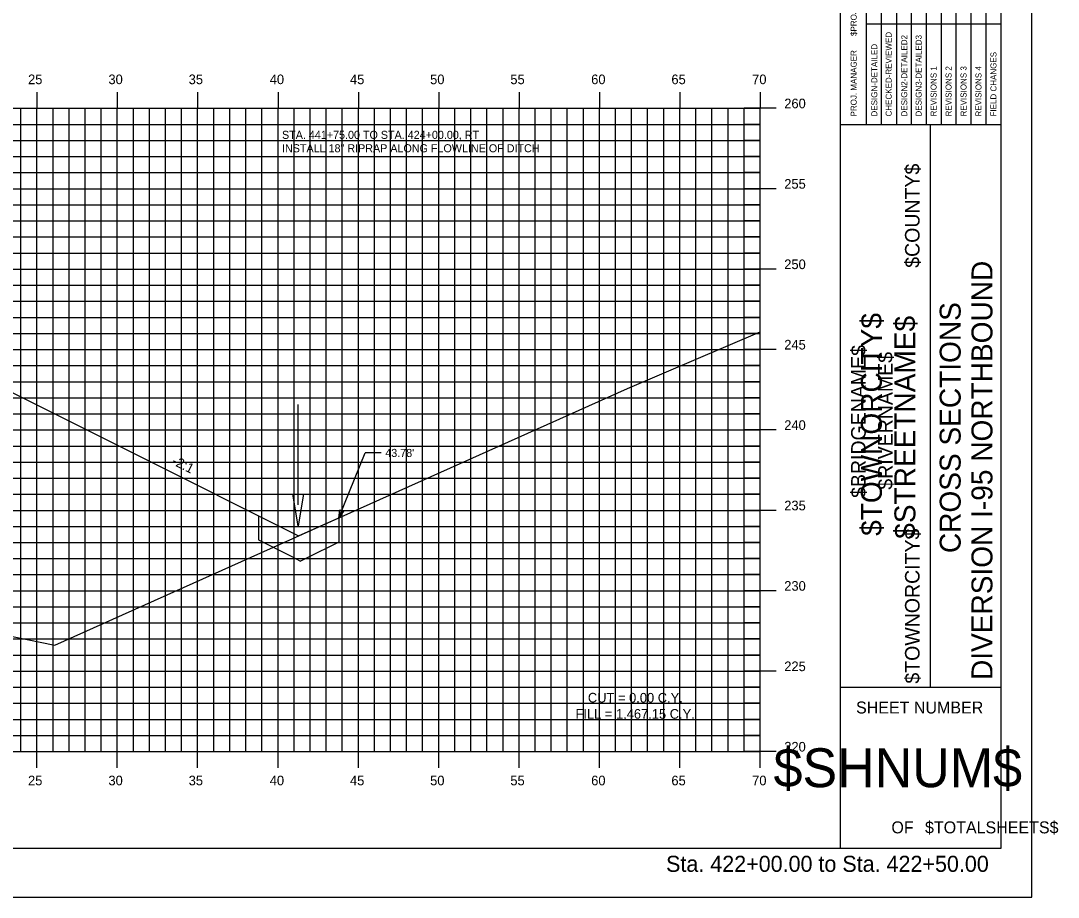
# Model space of a CAD drawing. Extents: x 1160718 to 1173142, y 616002 to 617630.
# Drawn here: x 1169986.4 to 1170050.9, y 616613.9 to 616668.4 of the extents above; entities that cross this region are included whole.
import ezdxf

# ---------------------------------------------------------------- set-up
doc = ezdxf.new("R2010")
doc.units = 0
for name, color, linetype in [('ANNOTATION', 7, 'Continuous'), ('BORDER', 7, 'Continuous'), ('BRIDGE_TITLE', 7, 'Continuous'), ('D_Drainage_Ditch_Line', 7, 'Continuous'), ('D_Roadway_Centerline', 7, 'Continuous'), ('H_V ANNOTATION', 7, 'Continuous'), ('HIGHWAY_TITLE', 7, 'Continuous'), ('MAJOR', 7, 'Continuous'), ('MINOR', 7, 'Continuous'), ('PLOT BOUNDARY', 7, 'Continuous'), ('S_Roadway_Centerline', 7, 'Continuous')]:
    doc.layers.add(name, color=color, linetype=linetype)

msp = doc.modelspace()

# ---------------------------------------------------------------- linework, layer by layer
at = {"layer": 'ANNOTATION'}
for p in [(1170006.171, 616637.458), (1170008.818, 616641.498)]:
    msp.add_line(p, (1170007.818, 616641.498), dxfattribs=at)
for points in [[(1170001.171, 616637.589), (1170003.671, 616636.339), (1170006.171, 616637.458), (1170006.171, 616635.958), (1170004.171, 616634.958), (1170003.802, 616634.773)], [(1170001.171, 616637.589), (1170001.171, 616636.089), (1170003.171, 616635.089), (1170003.802, 616634.773)]]:
    msp.add_lwpolyline(points, dxfattribs=at)
msp.add_lwpolyline([(1170006.475, 616637.873), (1170006.171, 616637.458), (1170006.244, 616637.968)], close=True, dxfattribs=at)
at = {"layer": 'BORDER'}
for p, q in [((1170037.394, 616616.931), (1170037.394, 616721.931)), ((1170047.394, 616616.931), (1170047.394, 616721.931)), ((1170037.394, 616661.931), (1170047.394, 616661.931)), ((1170042.985, 616626.931), (1170042.985, 616661.931)), ((1170037.394, 616626.931), (1170047.394, 616626.931)), ((1169887.394, 616616.928), (1170047.394, 616616.928))]:
    msp.add_line(p, q, dxfattribs=at)
for points in [[(1170039.942, 616661.934), (1170039.942, 616679.431)], [(1170040.873, 616679.431), (1170040.873, 616661.934)], [(1170041.805, 616661.934), (1170041.805, 616679.431)], [(1170042.737, 616661.934), (1170042.737, 616679.431)], [(1170043.668, 616661.934), (1170043.668, 616679.431)], [(1170044.6, 616661.934), (1170044.6, 616679.431)], [(1170045.532, 616661.934), (1170045.532, 616679.431)], [(1170046.463, 616661.934), (1170046.463, 616679.431)], [(1170039.01, 616661.934), (1170039.01, 616678.725)], [(1170039.009, 616668.181), (1170047.394, 616668.181)]]:
    msp.add_lwpolyline(points, dxfattribs=at)
at = {"layer": 'D_Drainage_Ditch_Line'}
msp.add_line((1170003.648, 616638.271), (1170003.649, 616644.515), dxfattribs=at)
msp.add_lwpolyline([(1170003.32, 616638.928), (1170003.976, 616638.928), (1170003.648, 616636.959)], close=True, dxfattribs=at)
at = {"layer": 'D_Roadway_Centerline'}
for p, q in [((1169982.394, 616646.977), (1169987.597, 616644.376)), ((1169987.597, 616644.376), (1169993.477, 616641.436)), ((1169993.477, 616641.436), (1170003.671, 616636.339))]:
    msp.add_line(p, q, dxfattribs=at)
at = {"layer": 'MAJOR'}
for p, q in [((1169987.394, 616663.93), (1169987.394, 616662.928)), ((1169992.394, 616663.93), (1169992.394, 616662.928)), ((1169997.394, 616663.93), (1169997.394, 616662.928)), ((1170002.394, 616663.93), (1170002.394, 616662.928)), ((1170007.394, 616663.93), (1170007.394, 616662.928)), ((1170012.394, 616663.93), (1170012.394, 616662.928)), ((1170017.394, 616663.93), (1170017.394, 616662.928)), ((1170022.394, 616663.93), (1170022.394, 616662.928)), ((1170027.394, 616663.93), (1170027.394, 616662.928)), ((1170032.394, 616663.93), (1170032.394, 616662.928)), ((1169892.394, 616662.928), (1170032.394, 616662.928)), ((1169892.394, 616662.928), (1170032.394, 616662.928)), ((1169987.394, 616622.928), (1169987.394, 616662.928)), ((1169992.394, 616622.928), (1169992.394, 616662.928)), ((1169997.394, 616622.928), (1169997.394, 616662.928)), ((1170002.394, 616622.928), (1170002.394, 616662.928)), ((1170007.394, 616622.928), (1170007.394, 616662.928)), ((1170012.394, 616622.928), (1170012.394, 616662.928)), ((1170017.394, 616622.928), (1170017.394, 616662.928)), ((1170022.394, 616622.928), (1170022.394, 616662.928)), ((1170027.394, 616622.928), (1170027.394, 616662.928)), ((1170033.396, 616662.928), (1170031.392, 616662.928)), ((1170032.394, 616622.928), (1170032.394, 616662.928)), ((1170032.394, 616622.928), (1170032.394, 616662.928)), ((1169892.394, 616657.928), (1170032.394, 616657.928)), ((1170033.396, 616657.928), (1170031.392, 616657.928)), ((1169892.394, 616652.928), (1170032.394, 616652.928)), ((1170033.396, 616652.928), (1170031.392, 616652.928)), ((1169892.394, 616647.928), (1170032.394, 616647.928)), ((1170033.396, 616647.928), (1170031.392, 616647.928)), ((1169892.394, 616642.928), (1170032.394, 616642.928)), ((1170033.396, 616642.928), (1170031.392, 616642.928)), ((1169892.394, 616637.928), (1170032.394, 616637.928)), ((1170033.396, 616637.928), (1170031.392, 616637.928)), ((1169892.394, 616632.928), (1170032.394, 616632.928)), ((1170033.396, 616632.928), (1170031.392, 616632.928)), ((1169892.394, 616627.928), (1170032.394, 616627.928)), ((1170033.396, 616627.928), (1170031.392, 616627.928)), ((1169892.394, 616622.928), (1170032.394, 616622.928)), ((1169892.394, 616622.928), (1170032.394, 616622.928)), ((1169987.394, 616621.926), (1169987.394, 616622.928)), ((1169992.394, 616621.926), (1169992.394, 616622.928)), ((1169997.394, 616621.926), (1169997.394, 616622.928)), ((1170002.394, 616621.926), (1170002.394, 616622.928)), ((1170007.394, 616621.926), (1170007.394, 616622.928)), ((1170012.394, 616621.926), (1170012.394, 616622.928)), ((1170017.394, 616621.926), (1170017.394, 616622.928)), ((1170022.394, 616621.926), (1170022.394, 616622.928)), ((1170027.394, 616621.926), (1170027.394, 616622.928)), ((1170033.396, 616622.928), (1170031.392, 616622.928)), ((1170032.394, 616621.926), (1170032.394, 616622.928))]:
    msp.add_line(p, q, dxfattribs=at)
at = {"layer": 'MINOR'}
for p, q in [((1169986.394, 616622.928), (1169986.394, 616662.928)), ((1169988.394, 616622.928), (1169988.394, 616662.928)), ((1169989.394, 616622.928), (1169989.394, 616662.928)), ((1169990.394, 616622.928), (1169990.394, 616662.928)), ((1169991.394, 616622.928), (1169991.394, 616662.928)), ((1169993.394, 616622.928), (1169993.394, 616662.928)), ((1169994.394, 616622.928), (1169994.394, 616662.928)), ((1169995.394, 616622.928), (1169995.394, 616662.928)), ((1169996.394, 616622.928), (1169996.394, 616662.928)), ((1169998.394, 616622.928), (1169998.394, 616662.928)), ((1169999.394, 616622.928), (1169999.394, 616662.928)), ((1170000.394, 616622.928), (1170000.394, 616662.928)), ((1170001.394, 616622.928), (1170001.394, 616662.928)), ((1170003.394, 616622.928), (1170003.394, 616662.928)), ((1170004.394, 616622.928), (1170004.394, 616662.928)), ((1170005.394, 616622.928), (1170005.394, 616662.928)), ((1170006.394, 616622.928), (1170006.394, 616662.928)), ((1170008.394, 616622.928), (1170008.394, 616662.928)), ((1170009.394, 616622.928), (1170009.394, 616662.928)), ((1170010.394, 616622.928), (1170010.394, 616662.928)), ((1170011.394, 616622.928), (1170011.394, 616662.928)), ((1170013.394, 616622.928), (1170013.394, 616662.928)), ((1170014.394, 616622.928), (1170014.394, 616662.928)), ((1170015.394, 616622.928), (1170015.394, 616662.928)), ((1170016.394, 616622.928), (1170016.394, 616662.928)), ((1170018.394, 616622.928), (1170018.394, 616662.928)), ((1170019.394, 616622.928), (1170019.394, 616662.928)), ((1170020.394, 616622.928), (1170020.394, 616662.928)), ((1170021.394, 616622.928), (1170021.394, 616662.928)), ((1170023.394, 616622.928), (1170023.394, 616662.928)), ((1170024.394, 616622.928), (1170024.394, 616662.928)), ((1170025.394, 616622.928), (1170025.394, 616662.928)), ((1170026.394, 616622.928), (1170026.394, 616662.928)), ((1170028.394, 616622.928), (1170028.394, 616662.928)), ((1170029.394, 616622.928), (1170029.394, 616662.928)), ((1170030.394, 616622.928), (1170030.394, 616662.928)), ((1170031.394, 616622.928), (1170031.394, 616662.928)), ((1169892.394, 616661.928), (1170032.394, 616661.928)), ((1170032.394, 616661.928), (1170031.392, 616661.928)), ((1169892.394, 616660.928), (1170032.394, 616660.928)), ((1170032.394, 616660.928), (1170031.392, 616660.928)), ((1169892.394, 616659.928), (1170032.394, 616659.928)), ((1170032.394, 616659.928), (1170031.392, 616659.928)), ((1169892.394, 616658.928), (1170032.394, 616658.928)), ((1170032.394, 616658.928), (1170031.392, 616658.928)), ((1169892.394, 616656.928), (1170032.394, 616656.928)), ((1170032.394, 616656.928), (1170031.392, 616656.928)), ((1169892.394, 616655.928), (1170032.394, 616655.928)), ((1170032.394, 616655.928), (1170031.392, 616655.928)), ((1169892.394, 616654.928), (1170032.394, 616654.928)), ((1170032.394, 616654.928), (1170031.392, 616654.928)), ((1169892.394, 616653.928), (1170032.394, 616653.928)), ((1170032.394, 616653.928), (1170031.392, 616653.928)), ((1169892.394, 616651.928), (1170032.394, 616651.928)), ((1170032.394, 616651.928), (1170031.392, 616651.928)), ((1169892.394, 616650.928), (1170032.394, 616650.928)), ((1170032.394, 616650.928), (1170031.392, 616650.928)), ((1169892.394, 616649.928), (1170032.394, 616649.928)), ((1170032.394, 616649.928), (1170031.392, 616649.928)), ((1169892.394, 616648.928), (1170032.394, 616648.928)), ((1170032.394, 616648.928), (1170031.392, 616648.928)), ((1169892.394, 616646.928), (1170032.394, 616646.928)), ((1170032.394, 616646.928), (1170031.392, 616646.928)), ((1169892.394, 616645.928), (1170032.394, 616645.928)), ((1170032.394, 616645.928), (1170031.392, 616645.928)), ((1169892.394, 616644.928), (1170032.394, 616644.928)), ((1170032.394, 616644.928), (1170031.392, 616644.928)), ((1169892.394, 616643.928), (1170032.394, 616643.928)), ((1170032.394, 616643.928), (1170031.392, 616643.928)), ((1169892.394, 616641.928), (1170032.394, 616641.928)), ((1170032.394, 616641.928), (1170031.392, 616641.928)), ((1169892.394, 616640.928), (1170032.394, 616640.928)), ((1170032.394, 616640.928), (1170031.392, 616640.928)), ((1169892.394, 616639.928), (1170032.394, 616639.928)), ((1170032.394, 616639.928), (1170031.392, 616639.928)), ((1169892.394, 616638.928), (1170032.394, 616638.928)), ((1170032.394, 616638.928), (1170031.392, 616638.928)), ((1169892.394, 616636.928), (1170032.394, 616636.928)), ((1170032.394, 616636.928), (1170031.392, 616636.928)), ((1169892.394, 616635.928), (1170032.394, 616635.928)), ((1170032.394, 616635.928), (1170031.392, 616635.928)), ((1169892.394, 616634.928), (1170032.394, 616634.928)), ((1170032.394, 616634.928), (1170031.392, 616634.928)), ((1169892.394, 616633.928), (1170032.394, 616633.928)), ((1170032.394, 616633.928), (1170031.392, 616633.928)), ((1169892.394, 616631.928), (1170032.394, 616631.928)), ((1170032.394, 616631.928), (1170031.392, 616631.928)), ((1169892.394, 616630.928), (1170032.394, 616630.928)), ((1170032.394, 616630.928), (1170031.392, 616630.928)), ((1169892.394, 616629.928), (1170032.394, 616629.928)), ((1170032.394, 616629.928), (1170031.392, 616629.928)), ((1169892.394, 616628.928), (1170032.394, 616628.928)), ((1170032.394, 616628.928), (1170031.392, 616628.928)), ((1169892.394, 616626.928), (1170032.394, 616626.928)), ((1170032.394, 616626.928), (1170031.392, 616626.928)), ((1169892.394, 616625.928), (1170032.394, 616625.928)), ((1170032.394, 616625.928), (1170031.392, 616625.928)), ((1169892.394, 616624.928), (1170032.394, 616624.928)), ((1170032.394, 616624.928), (1170031.392, 616624.928)), ((1169892.394, 616623.928), (1170032.394, 616623.928)), ((1170032.394, 616623.928), (1170031.392, 616623.928))]:
    msp.add_line(p, q, dxfattribs=at)
at = {"layer": 'PLOT BOUNDARY'}
msp.add_lwpolyline([(1169879.301, 616613.869), (1170049.301, 616613.869), (1170049.301, 616723.869), (1169879.301, 616723.869)], close=True, dxfattribs=at)
at = {"layer": 'S_Roadway_Centerline'}
msp.add_lwpolyline([(1169892.394, 616656.192), (1169916.374, 616644.577), (1169917.207, 616644.209), (1169918.636, 616643.902), (1169948.404, 616635.612), (1169963.662, 616634.32), (1169973.379, 616632.837), (1169981.1, 616631.066), (1169988.505, 616629.55), (1170024.144, 616645.503), (1170032.394, 616649.032)], dxfattribs=at)

# ---------------------------------------------------------------- texts
at = {"layer": 'ANNOTATION'}
for s, p in [('STA. 441+75.00 TO STA. 424+00.00, RT', (1170002.642, 616661.028)), ('INSTALL 18" RIPRAP ALONG FLOWLINE OF DITCH', (1170002.642, 616660.193)), ("43.78'", (1170009.068, 616641.248))]:
    msp.add_text(s, height=0.5, dxfattribs=at).set_placement(p)
for s, rotation, p in [('-2:1', 333.43495, (1169995.746, 616640.819)), ('CUT = 0.00 C.Y.', 359.92408, (1170021.674, 616625.978)), ('FILL = 1,467.15 C.Y.', 359.92408, (1170020.902, 616624.977))]:
    msp.add_text(s, height=0.6, rotation=rotation, dxfattribs=at).set_placement(p)
at = {"layer": 'BORDER'}
for s, height, rotation, p in [('$PROJMANAGER$', 0.37275, 90, (1170038.398, 616667.426)), ('CHECKED-REVIEWED', 0.37275, 90, (1170040.575, 616662.419)), ('DESIGN2-DETAILED2', 0.37275, 90, (1170041.544, 616662.419)), ('DESIGN3-DETAILED3', 0.37275, 90, (1170042.439, 616662.419)), ('DESIGN-DETAILED', 0.37275, 90, (1170039.681, 616662.419)), ('PROJ. MANAGER', 0.37275, 90, (1170038.398, 616662.419)), ('FIELD CHANGES', 0.37275, 90, (1170047.097, 616662.419)), ('REVISIONS 1', 0.37275, 90, (1170043.37, 616662.419)), ('REVISIONS 2', 0.37275, 90, (1170044.302, 616662.419)), ('REVISIONS 3', 0.37275, 90, (1170045.234, 616662.419)), ('REVISIONS 4', 0.37275, 90, (1170046.165, 616662.419)), ('DIVERSION I-95 NORTHBOUND  ', 1.30428, 90, (1170046.848, 616627.379)), ('CROSS SECTIONS', 1.30428, 90, (1170044.87, 616635.27)), ('SHEET NUMBER', 0.74527, 360, (1170038.36, 616625.295)), ('$SHNUM$', 2.4194, 360, (1170033.227, 616620.711)), ('OF', 0.7453, 360, (1170040.561, 616617.841)), ('$TOTALSHEETS$', 0.74527, 360, (1170042.651, 616617.841))]:
    msp.add_text(s, height=height, rotation=rotation, dxfattribs=at).set_placement(p)
at = {"layer": 'BRIDGE_TITLE'}
for s, height, p in [('$COUNTY$', 0.9072, (1170042.314, 616653.011)), ('$BRIDGENAME$', 0.90716, (1170038.96, 616638.7)), ('$RIVERNAME$', 0.90716, (1170040.637, 616639.214)), ('$TOWNORCITY$', 0.90716, (1170042.314, 616627.152))]:
    msp.add_text(s, height=height, rotation=90, dxfattribs=at).set_placement(p)
at = {"layer": 'H_V ANNOTATION'}
for s, height, p in [('25', 0.6, (1169986.84, 616664.428)), ('30', 0.6, (1169991.843, 616664.428)), ('35', 0.6, (1169996.835, 616664.428)), ('40', 0.6, (1170001.88, 616664.428)), ('45', 0.6, (1170006.872, 616664.428)), ('50', 0.6, (1170011.859, 616664.428)), ('55', 0.6, (1170016.851, 616664.428)), ('60', 0.6, (1170021.88, 616664.428)), ('65', 0.6, (1170026.872, 616664.428)), ('70', 0.6, (1170031.896, 616664.428)), ('260', 0.6, (1170033.894, 616662.928)), ('255', 0.6, (1170033.894, 616657.928)), ('250', 0.6, (1170033.894, 616652.928)), ('245', 0.6, (1170033.894, 616647.928)), ('240', 0.6, (1170033.894, 616642.928)), ('235', 0.6, (1170033.894, 616637.928)), ('230', 0.6, (1170033.894, 616632.928)), ('225', 0.6, (1170033.894, 616627.928)), ('220', 0.6, (1170033.894, 616622.928)), ('25', 0.6, (1169986.84, 616620.828)), ('30', 0.6, (1169991.843, 616620.828)), ('35', 0.6, (1169996.835, 616620.828)), ('40', 0.6, (1170001.88, 616620.828)), ('45', 0.6, (1170006.872, 616620.828)), ('50', 0.6, (1170011.859, 616620.828)), ('55', 0.6, (1170016.851, 616620.828)), ('60', 0.6, (1170021.88, 616620.828)), ('65', 0.6, (1170026.872, 616620.828)), ('70', 0.6, (1170031.896, 616620.828)), ('Sta. 422+00.00 to Sta. 422+50.00', 1.0002, (1170026.54, 616615.448))]:
    msp.add_text(s, height=height, dxfattribs=at).set_placement(p)
at = {"layer": 'HIGHWAY_TITLE'}
for s, p in [('$TOWNORCITY$', (1170039.967, 616636.34)), ('$STREETNAME$', (1170042.054, 616636.16))]:
    msp.add_text(s, height=1.30428, rotation=90, dxfattribs=at).set_placement(p)

doc.saveas('drawing.dxf')
